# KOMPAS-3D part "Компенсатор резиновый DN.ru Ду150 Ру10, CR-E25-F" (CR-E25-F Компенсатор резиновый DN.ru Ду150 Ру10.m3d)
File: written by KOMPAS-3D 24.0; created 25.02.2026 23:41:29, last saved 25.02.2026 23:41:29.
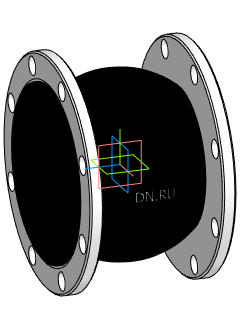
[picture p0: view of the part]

Document properties: Автор: DN.RU; Полное имя файла: D:\PROJECT CAD\DN.RU\...178(4)(ACTUALE). CR-E25-F Компенсатор резиновый DN.ru Ру10-16\DN150_PN10\CR-E25-F Компенсатор резиновый DN.ru Ду150 Ру10.m3d

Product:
- Body: Твердое тело2  | qty 1
    Масса: 25.350854
- Part/product: Компенсатор резиновый DN.ru Ду150 Ру10  | designation CR-E25-F
    Масса: 13.13
    Раздел спецификации: Прочие изделия
    Комментарий: D140-02167
    Примечание: D140-02167
    additional columns: Типовые

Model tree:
1. Твердое тело2  (labels: Твердое тело2)

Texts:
  CR-E25-F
